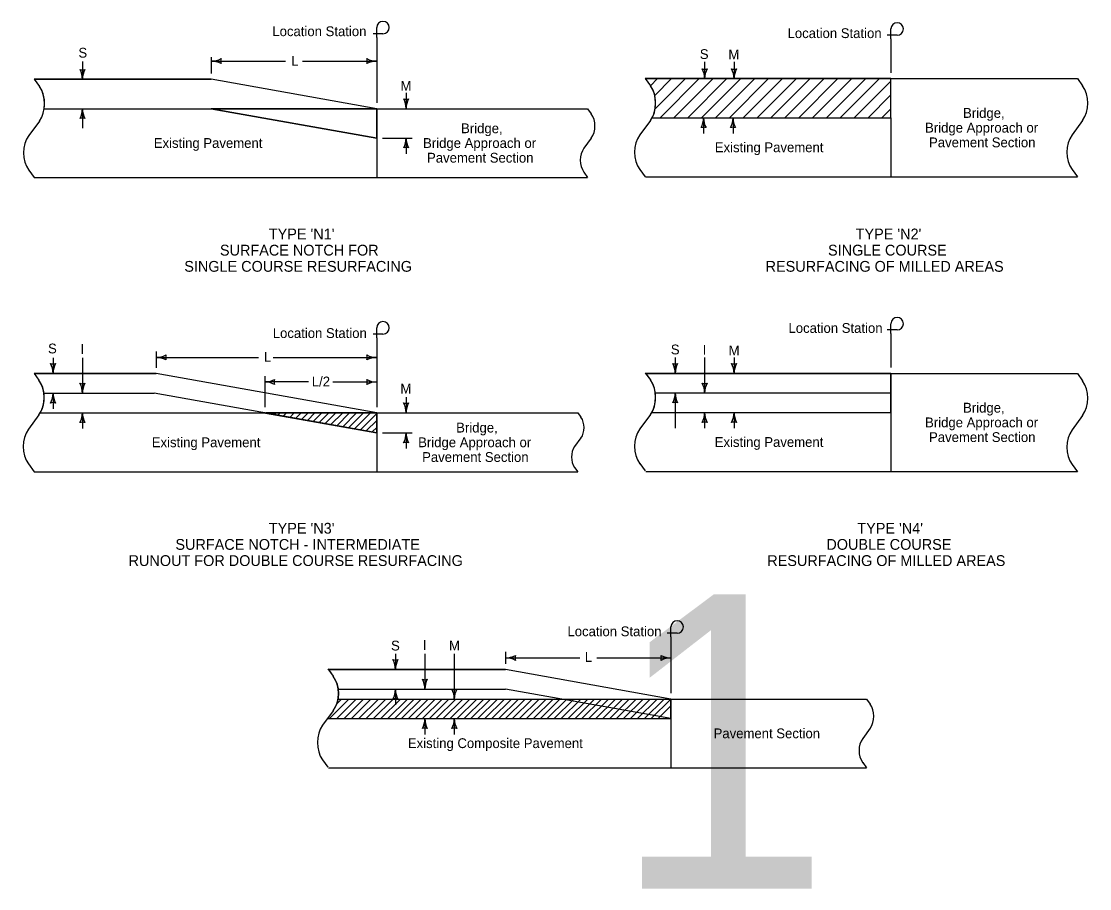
# Model space of a CAD drawing. Extents: x 10133 to 81668, y 7924 to 12178.
# Drawn here: x 10292 to 12471, y 10409 to 12178 of the extents above; entities that cross this region are included whole.
import ezdxf

# ---------------------------------------------------------------- set-up
doc = ezdxf.new("R2010")
doc.units = 0
for name, color, linetype in [('Default', 7, 'Continuous'), ('dsnNonPlotable', 7, 'Continuous'), ('dsnShadingPaved', 7, 'Continuous'), ('dsnShtPlotShapeBatchPrint', 7, 'Continuous'), ('dsnStdBlock', 7, 'Continuous'), ('dsnstdblockInterim', 7, 'Continuous'), ('dsnStdBlockModified', 7, 'Continuous'), ('dsnStdBlockNotModified', 7, 'Continuous'), ('dsnStdBorder', 7, 'Continuous'), ('Level 2', 7, 'Continuous')]:
    doc.layers.add(name, color=color, linetype=linetype)

msp = doc.modelspace()

# ---------------------------------------------------------------- linework, layer by layer
at = {"layer": 'Default'}
for p, q in [((11017.1, 11999.6), (10679.6, 11999.6)), ((10679.6, 11999.6), (11017.1, 11939.6)), ((11017.1, 11939.6), (11017.1, 11999.6))]:
    msp.add_line(p, q, dxfattribs=at)
msp.add_lwpolyline([(10790.5, 11379), (11017.1, 11338.7), (11017.1, 11379.3), (10790.9, 11379.3), (10790.5, 11379)], dxfattribs=at)
at = {"layer": 'dsnNonPlotable'}
for p, q in [((10318.5, 12059.6), (10329.2, 12045)), ((11017.1, 11999.6), (10679.6, 12059.6)), ((12065.7, 12060.9), (11564.4, 12060.9)), ((11564.4, 12060.9), (11575.2, 12046.3)), ((12065.7, 11980.9), (12065.7, 12060.9)), ((10679.6, 11999.6), (11017.1, 11939.6)), ((11017.1, 11939.6), (11017.1, 11999.6)), ((11578.6, 11980.9), (12065.7, 11980.9)), ((10567.1, 11459.3), (10318.5, 11459.3)), ((10318.5, 11459.3), (10328.3, 11446)), ((11017.1, 11379.3), (10567.1, 11459.3)), ((10330.9, 11379.3), (11017.1, 11379.3))]:
    msp.add_line(p, q, dxfattribs=at)
for points in [[(10679.6, 12059.6), (10417.1, 12059.6), (10318.5, 12059.6)], [(10339.2, 11999.6), (10417.1, 11999.6), (10679.6, 11999.6)]]:
    msp.add_lwpolyline(points, dxfattribs=at)
for centre, start_param in [((11549.2, 12010.9), 0.927277), ((10303.3, 12009.6), 1.369431), ((10302.4, 11410.6), 0.895403)]:
    msp.add_ellipse(centre, major_axis=(0, -50), ratio=0.732645, start_param=start_param, end_param=2.356194, dxfattribs=at)
at = {"layer": 'dsnShtPlotShapeBatchPrint'}
for p, q in [((11575.2, 12046.2), (11589.9, 12060.9)), ((11584, 12026.7), (11618.2, 12060.9)), ((11584.9, 11999.3), (11646.5, 12060.9)), ((11594.7, 11980.9), (11674.7, 12060.9)), ((11623, 11980.9), (11703, 12060.9)), ((11651.3, 11980.9), (11731.3, 12060.9)), ((11679.6, 11980.9), (11759.6, 12060.9)), ((11707.9, 11980.9), (11787.9, 12060.9)), ((11736.2, 11980.9), (11816.2, 12060.9)), ((11764.5, 11980.9), (11844.5, 12060.9)), ((11792.7, 11980.9), (11872.7, 12060.9)), ((11821, 11980.9), (11901, 12060.9)), ((11849.3, 11980.9), (11929.3, 12060.9)), ((11877.6, 11980.9), (11957.6, 12060.9)), ((11905.9, 11980.9), (11985.9, 12060.9)), ((11934.2, 11980.9), (12014.2, 12060.9)), ((11962.4, 11980.9), (12042.4, 12060.9)), ((11990.7, 11980.9), (12065.7, 12055.9)), ((12019, 11980.9), (12065.7, 12027.6)), ((12047.3, 11980.9), (12065.7, 11999.3))]:
    msp.add_line(p, q, dxfattribs=at)
at = {"layer": 'dsnStdBlock'}
for p, q in [((11017.1, 12144.6), (11017.1, 12165)), ((12065.7, 12141.9), (12065.7, 12162.2)), ((11029.8, 12152.3), (11009.5, 12152.3)), ((11017.1, 12144.6), (11017.1, 12011.6)), ((12078.4, 12149.5), (12058.1, 12149.5)), ((12065.7, 12141.9), (12065.7, 12072.9)), ((10417.1, 12096), (10417.1, 12059.6)), ((10679.6, 12104.6), (10679.6, 12071.6)), ((10679.6, 12096.6), (10830.9, 12096.6)), ((10865.9, 12096.6), (11017.1, 12096.6)), ((11685.7, 12095.4), (11685.7, 12060.9)), ((11745.7, 12095.4), (11745.7, 12060.9)), ((10318.5, 12059.6), (10679.6, 12059.6)), ((10318.5, 12059.6), (10329.2, 12045)), ((11017.1, 11999.6), (10679.6, 12059.6)), ((11564.4, 12060.9), (12065.7, 12060.9)), ((11564.4, 12060.9), (11575.1, 12046.3)), ((12065.7, 12060.9), (12445.7, 12060.9)), ((12065.7, 11980.9), (12065.7, 12060.9)), ((12445.7, 12060.9), (12456.4, 12046.3)), ((11077.1, 12031.9), (11077.1, 11999.9)), ((10339.2, 11999.6), (10679.6, 11999.6)), ((10417.1, 11999.6), (10417.1, 11960.2)), ((11017.1, 11939.6), (10679.6, 11999.6)), ((10679.6, 11999.6), (11017.1, 11999.6)), ((11017.1, 11999.6), (11446.9, 11999.6)), ((11017.1, 11999.6), (11017.1, 11939.6)), ((11447.1, 11999.4), (11454.6, 11989.1)), ((11578.6, 11980.9), (12065.7, 11980.9)), ((11683.6, 11980.9), (11683.6, 11948.9)), ((11743.6, 11980.9), (11743.6, 11948.9)), ((12065.7, 11980.9), (12065.7, 11860.9)), ((10329.2, 11974.3), (10307.7, 11945)), ((11575.1, 11975.5), (11553.7, 11946.3)), ((12456.4, 11975.5), (12435, 11946.3)), ((11017.1, 11939.6), (11017.1, 11859.6)), ((11029.1, 11939.6), (11089.1, 11939.6)), ((11077.1, 11939.6), (11077.1, 11907.6)), ((11454.6, 11939.7), (11439.6, 11919.3)), ((10307.7, 11874.3), (10318.5, 11859.6)), ((11553.7, 11875.5), (11564.4, 11860.9)), ((12435, 11875.5), (12445.7, 11860.9)), ((10318.5, 11859.6), (11447.1, 11859.6)), ((11439.6, 11869.9), (11447.1, 11859.6)), ((11565.3, 11860.9), (12445.7, 11860.9)), ((11017.1, 11532.3), (11017.1, 11552.7)), ((12078.4, 11548.5), (12058.1, 11548.5)), ((12065.7, 11540.9), (12065.7, 11561.2)), ((11029.8, 11540), (11009.5, 11540)), ((11017.1, 11532.3), (11017.1, 11391.3)), ((12065.7, 11540.9), (12065.7, 11471.9)), ((10567.1, 11504.3), (10567.1, 11471.3)), ((10357.1, 11491.7), (10357.1, 11459.7)), ((10417.1, 11491.7), (10417.1, 11419.3)), ((10567.1, 11492.3), (10776.1, 11492.3)), ((10806.1, 11492.3), (11017.1, 11492.3)), ((11625.7, 11491.9), (11625.7, 11459.9)), ((11685.7, 11491.9), (11685.7, 11419.9)), ((11745.7, 11491.9), (11745.7, 11459.9)), ((10318.5, 11459.3), (10567.1, 11459.3)), ((10318.5, 11459.3), (10328.3, 11446)), ((11017.1, 11379.3), (10567.1, 11459.3)), ((11564.4, 11461.1), (11575.1, 11446.5)), ((11565.7, 11459.9), (12065.7, 11459.9)), ((12065.7, 11459.9), (12065.7, 11379.9)), ((12065.7, 11459.9), (12445.7, 11459.9)), ((12445.7, 11459.9), (12456.4, 11444.7)), ((10788.6, 11454.3), (10788.6, 11391.3)), ((10877.8, 11442.3), (10788.6, 11442.3)), ((10927.8, 11442.3), (11017.1, 11442.3)), ((10338.4, 11419.3), (10563.6, 11419.3)), ((10357.1, 11419.7), (10357.1, 11387.7)), ((11017.1, 11338.7), (10563.6, 11419.3)), ((11585.3, 11419.9), (12065.7, 11419.9)), ((11625.7, 11419.9), (11625.7, 11347.9)), ((11077.1, 11411.3), (11077.1, 11379.3)), ((10328.3, 11375.2), (10306.8, 11346)), ((10330.9, 11379.3), (11017.1, 11379.3)), ((10417.1, 11379.7), (10417.1, 11347.7)), ((10788.6, 11379.3), (10788.6, 11379.3)), ((10789.3, 11379.2), (10789.5, 11379.3)), ((10790.5, 11379), (10790.9, 11379.3)), ((10803.7, 11376.7), (10806.4, 11379.3)), ((10808.5, 11375.8), (10812, 11379.3)), ((10815.7, 11374.5), (10820.5, 11379.3)), ((10826.5, 11372.6), (10833.2, 11379.3)), ((10839.7, 11370.2), (10848.8, 11379.3)), ((10851.7, 11368.1), (10862.9, 11379.3)), ((10863.7, 11366), (10877.1, 11379.3)), ((10875.7, 11363.8), (10891.2, 11379.3)), ((10887.7, 11361.7), (10905.4, 11379.3)), ((10899.7, 11359.6), (10919.5, 11379.3)), ((10911.7, 11357.4), (10933.6, 11379.3)), ((10923.7, 11355.3), (10947.8, 11379.3)), ((10935.8, 11353.2), (10961.9, 11379.3)), ((10947.8, 11351), (10976.1, 11379.3)), ((10959.8, 11348.9), (10990.2, 11379.3)), ((10971.8, 11346.8), (11004.3, 11379.3)), ((10983.8, 11344.6), (11017.1, 11377.9)), ((11017.1, 11379.3), (11427.1, 11379.3)), ((11017.1, 11379.3), (11017.1, 11338.7)), ((11427.1, 11379.3), (11433.5, 11370.5)), ((11575.1, 11375.8), (11553.7, 11346.5)), ((11578.1, 11379.9), (12065.7, 11379.9)), ((11685.7, 11379.9), (11685.7, 11347.9)), ((11745.7, 11379.9), (11745.7, 11347.9)), ((12065.4, 11379.9), (12065.7, 11380.2)), ((12065.7, 11379.9), (12065.7, 11259.9)), ((12456.4, 11374), (12435, 11344.7)), ((10995.8, 11342.5), (11017.1, 11363.8)), ((11007.8, 11340.4), (11017.1, 11349.7)), ((11017.1, 11338.7), (11017.1, 11259.3)), ((11029.1, 11338.7), (11089.1, 11338.7)), ((11077.1, 11338.7), (11077.1, 11306.7)), ((11433.5, 11328.1), (11420.7, 11310.5)), ((10306.8, 11275.2), (10318.8, 11259.3)), ((11420.7, 11268.1), (11427.1, 11259.3)), ((11553.7, 11275.8), (11564.4, 11261.1)), ((12435, 11274), (12445.7, 11259.3)), ((10318.8, 11259.3), (11427.1, 11259.3)), ((11565.7, 11259.9), (12445.7, 11259.9)), ((11617.1, 10922.4), (11617.1, 10942.7)), ((11629.8, 10930), (11609.5, 10930)), ((11617.1, 10922.4), (11617.1, 10807.8)), ((11279.6, 10891.8), (11279.6, 10867.8)), ((11055.3, 10887.8), (11055.3, 10855.8)), ((11115.3, 10887.8), (11115.3, 10815.8)), ((11175.3, 10887.8), (11175.3, 10795.8)), ((11279.6, 10879.8), (11430.9, 10879.8)), ((11465.9, 10879.8), (11617.1, 10879.8)), ((10917.5, 10857.1), (10928.3, 10842.4)), ((10918.5, 10855.8), (11279.6, 10855.8)), ((11617.1, 10795.8), (11279.6, 10855.8)), ((10938.4, 10815.8), (11279.6, 10815.8)), ((11055.3, 10815.8), (11055.3, 10783.8)), ((11175.4, 10814.1), (11177.2, 10815.8)), ((11617.1, 10755.8), (11279.6, 10815.8)), ((10920.5, 10755.8), (10960.4, 10795.8)), ((10935.5, 10755.8), (10975.4, 10795.8)), ((10935.6, 10785.9), (10945.4, 10795.8)), ((10938.1, 10795.8), (11392.1, 10795.8)), ((10950.5, 10755.8), (10990.4, 10795.8)), ((10965.5, 10755.8), (11005.4, 10795.8)), ((10980.5, 10755.8), (11020.4, 10795.8)), ((10995.5, 10755.8), (11035.4, 10795.8)), ((11010.5, 10755.8), (11050.4, 10795.8)), ((11025.5, 10755.8), (11065.4, 10795.8)), ((11039.6, 10755.8), (11079.6, 10795.8)), ((11053.7, 10755.8), (11093.7, 10795.8)), ((11067.9, 10755.8), (11107.9, 10795.8)), ((11082, 10755.8), (11122, 10795.8)), ((11096.2, 10755.8), (11136.2, 10795.8)), ((11110.3, 10755.8), (11150.3, 10795.8)), ((11124.4, 10755.8), (11164.4, 10795.8)), ((11138.6, 10755.8), (11178.6, 10795.8)), ((11152.7, 10755.8), (11192.7, 10795.8)), ((11166.9, 10755.8), (11206.9, 10795.8)), ((11181, 10755.8), (11221, 10795.8)), ((11195.2, 10755.8), (11235.2, 10795.8)), ((11209.3, 10755.8), (11249.3, 10795.8)), ((11223.4, 10755.8), (11263.4, 10795.8)), ((11237.6, 10755.8), (11277.6, 10795.8)), ((11251.7, 10755.8), (11291.7, 10795.8)), ((11265.9, 10755.8), (11305.9, 10795.8)), ((11280, 10755.8), (11320, 10795.8)), ((11294.2, 10755.8), (11334.2, 10795.8)), ((11308.3, 10755.8), (11348.3, 10795.8)), ((11322.4, 10755.8), (11362.4, 10795.8)), ((11336.6, 10755.8), (11376.6, 10795.8)), ((11350.7, 10755.8), (11390.7, 10795.8)), ((11364.9, 10755.8), (11404.9, 10795.8)), ((11379, 10755.8), (11419, 10795.8)), ((11392.1, 10795.8), (11617.1, 10795.8)), ((11393.1, 10755.8), (11433.1, 10795.8)), ((11407.3, 10755.8), (11447.3, 10795.8)), ((11421.4, 10755.8), (11461.4, 10795.8)), ((11435.6, 10755.8), (11475.6, 10795.8)), ((11449.7, 10755.8), (11489.7, 10795.8)), ((11463.9, 10755.8), (11503.9, 10795.8)), ((11478, 10755.8), (11518, 10795.8)), ((11492.1, 10755.8), (11532.1, 10795.8)), ((11506.3, 10755.8), (11546.3, 10795.8)), ((11520.4, 10755.8), (11560.4, 10795.8)), ((11534.6, 10755.8), (11574.6, 10795.8)), ((11548.7, 10755.8), (11588.7, 10795.8)), ((11562.9, 10755.8), (11602.9, 10795.8)), ((11577, 10755.8), (11617, 10795.8)), ((11617.1, 10795.8), (11617.1, 10655.8)), ((11617.1, 10795.8), (12015.6, 10795.8)), ((12015.6, 10795.8), (12023.1, 10785.6)), ((10928.3, 10771.7), (10906.8, 10742.4)), ((11591.1, 10755.8), (11617.1, 10781.8)), ((10916.6, 10755.8), (11617.1, 10755.8)), ((11115.3, 10755.8), (11115.3, 10723.8)), ((11175.3, 10755.8), (11175.3, 10723.8)), ((12023.1, 10736.1), (12008.1, 10715.6)), ((10906.8, 10671.7), (10917.5, 10657.1)), ((10918.5, 10655.8), (12015.6, 10655.8)), ((12008.1, 10666.1), (12015.6, 10655.8))]:
    msp.add_line(p, q, dxfattribs=at)
msp.add_lwpolyline([(10788.6, 11379.3), (11017.1, 11379.3), (11017.1, 11338.7)], close=True, dxfattribs=at)
for centre, radius, start, end in [((11029.8, 12165), 12.7, 270, 180), ((12078.4, 12162.2), 12.7, 270, 180), ((12078.4, 11561.2), 12.7, 270, 180), ((11029.8, 11552.7), 12.7, 270, 180), ((10357.1, 11495.9), 16.7, 252.2666, 287.7333), ((10313.9, 11459.7), 43.2, 360, 28.0725), ((10400.3, 11459.7), 43.2, 151.9275, 180), ((10567.1, 11535.5), 43.2, 270, 298.0725), ((10567.1, 11449.2), 43.2, 61.9275, 90), ((10603.3, 11492.3), 16.7, 162.2666, 197.7334), ((10980.9, 11492.3), 16.7, 342.2666, 17.7333), ((11017.1, 11535.5), 43.2, 241.9275, 270), ((11017.1, 11449.2), 43.2, 90, 118.0725), ((10417.1, 11455.5), 16.7, 252.2666, 287.7333), ((10373.9, 11419.3), 43.2, 360, 28.0725), ((10460.3, 11419.3), 43.2, 151.9275, 180), ((10788.6, 11485.5), 43.2, 270, 298.0725), ((10788.6, 11399.2), 43.2, 61.9275, 90), ((10824.8, 11442.3), 16.7, 162.2666, 197.7334), ((10980.9, 11442.3), 16.7, 342.2666, 17.7333), ((11017.1, 11485.5), 43.2, 241.9275, 270), ((11017.1, 11399.2), 43.2, 90, 118.0725), ((10313.9, 11419.7), 43.2, 331.9275, 360), ((10400.3, 11419.7), 43.2, 180, 208.0725), ((10357.1, 11383.5), 16.7, 72.2666, 107.7334), ((11077.1, 11415.5), 16.7, 252.2666, 287.7333), ((11033.9, 11379.3), 43.2, 360, 28.0725), ((11120.3, 11379.3), 43.2, 151.9275, 180), ((10373.9, 11379.7), 43.2, 331.9275, 360), ((10460.3, 11379.7), 43.2, 180, 208.0725), ((10417.1, 11343.5), 16.7, 72.2666, 107.7334), ((11033.9, 11338.7), 43.2, 331.9275, 360), ((11120.3, 11338.7), 43.2, 180, 208.0725), ((11077.1, 11302.5), 16.7, 72.2666, 107.7334), ((11629.8, 10942.7), 12.7, 270, 180), ((11055.3, 10892), 16.7, 252.2666, 287.7333), ((11012.1, 10855.8), 43.2, 360, 28.0725), ((11098.4, 10855.8), 43.2, 151.9275, 180), ((11279.6, 10923), 43.2, 270, 298.0725), ((11279.6, 10836.6), 43.2, 61.9275, 90), ((11315.8, 10879.8), 16.7, 162.2666, 197.7334), ((11580.9, 10879.8), 16.7, 342.2666, 17.7333), ((11617.1, 10923), 43.2, 241.9275, 270), ((11617.1, 10836.6), 43.2, 90, 118.0725), ((11115.3, 10852), 16.7, 252.2666, 287.7333), ((11072.1, 10815.8), 43.2, 360, 28.0725), ((11158.4, 10815.8), 43.2, 151.9275, 180), ((11012.1, 10815.8), 43.2, 331.9275, 360), ((11098.4, 10815.8), 43.2, 180, 208.0725), ((11175.3, 10832), 16.7, 252.2666, 287.7333), ((11132.1, 10795.8), 43.2, 360, 28.0725), ((11218.4, 10795.8), 43.2, 151.9275, 180), ((11055.3, 10779.6), 16.7, 72.2666, 107.7334), ((11072.1, 10755.8), 43.2, 331.9275, 360), ((11158.4, 10755.8), 43.2, 180, 208.0725), ((11132.1, 10755.8), 43.2, 331.9275, 360), ((11218.4, 10755.8), 43.2, 180, 208.0725), ((11115.3, 10719.6), 16.7, 72.2666, 107.7334), ((11175.3, 10719.6), 16.7, 72.2666, 107.7334)]:
    msp.add_arc(centre, radius, start, end, dxfattribs=at)
for centre, major_axis, ratio in [((11549.2, 12010.9), (0, -50), 0.732645), ((12430.5, 12010.9), (0, -50), 0.732645), ((10303.3, 12009.6), (0, -50), 0.732645), ((11436.5, 11964.4), (0, -34.9), 0.732645), ((10333.6, 11909.6), (0, 50), 0.732645), ((11579.6, 11910.9), (0, 50), 0.732645), ((12460.9, 11910.9), (0, 50), 0.732645), ((11457.7, 11894.6), (0, 34.9), 0.732645), ((10302.4, 11410.6), (0, -50), 0.732645), ((11549.2, 11411.1), (0, -50), 0.732645), ((12430.5, 11409.3), (0, -50), 0.732645), ((11418, 11349.3), (0, -30), 0.732645), ((10332.7, 11310.6), (0, 50), 0.732645), ((11579.6, 11311.1), (0, 50), 0.732645), ((12460.9, 11309.3), (0, 50), 0.732645), ((11436.2, 11289.3), (0, 30), 0.732645), ((10902.4, 10807.1), (0, -50), 0.732645), ((12005, 10760.8), (0, -35), 0.732627), ((10932.7, 10707.1), (0, 50), 0.732645), ((12026.2, 10690.8), (0, 35), 0.732627)]:
    msp.add_ellipse(centre, major_axis=major_axis, ratio=ratio, start_param=0.785398, end_param=2.356194, dxfattribs=at)
at = {"layer": 'dsnStdBlockModified'}
for centre, radius, start, end in [((10679.6, 12139.1), 42.5, 270, 298.0725), ((10679.6, 12054.1), 42.5, 61.9275, 90), ((10715.2, 12096.6), 16.4, 162.2666, 197.7334), ((10981.5, 12096.6), 16.4, 342.2666, 17.7334), ((11017.1, 12139.1), 42.5, 241.9275, 270), ((11017.1, 12054.1), 42.5, 90, 118.0725), ((10417.1, 12095.3), 16.4, 252.2666, 287.7333), ((10374.6, 12059.6), 42.5, 360, 28.0725), ((10459.6, 12059.6), 42.5, 151.9275, 180), ((11685.7, 12096.5), 16.4, 252.2666, 287.7333), ((11643.2, 12060.9), 42.5, 360, 28.0725), ((11728.2, 12060.9), 42.5, 151.9275, 180), ((11745.7, 12096.5), 16.4, 252.2666, 287.7333), ((11703.2, 12060.9), 42.5, 360, 28.0725), ((11788.2, 12060.9), 42.5, 151.9275, 180), ((11077.1, 12035.5), 16.4, 252.2666, 287.7333), ((11034.6, 11999.9), 42.5, 360, 28.0725), ((11119.6, 11999.9), 42.5, 151.9275, 180), ((10374.6, 11999.6), 42.5, 331.9275, 360), ((10417.1, 11964), 16.4, 72.2666, 107.7334), ((10459.6, 11999.6), 42.5, 180, 208.0725), ((11641.1, 11980.9), 42.5, 331.9275, 360), ((11726.1, 11980.9), 42.5, 180, 208.0725), ((11701.1, 11980.9), 42.5, 331.9275, 360), ((11786.1, 11980.9), 42.5, 180, 208.0725), ((11683.6, 11945.3), 16.4, 72.2666, 107.7334), ((11743.6, 11945.3), 16.4, 72.2666, 107.7334), ((11034.6, 11939.6), 42.5, 331.9275, 360), ((11119.6, 11939.6), 42.5, 180, 208.0725), ((11077.1, 11904), 16.4, 72.2666, 107.7334), ((11625.7, 11495.5), 16.4, 252.2666, 287.7333), ((11583.2, 11459.9), 42.5, 360, 28.0725), ((11668.2, 11459.9), 42.5, 151.9275, 180), ((11745.7, 11495.5), 16.4, 252.2666, 287.7333), ((11703.2, 11459.9), 42.5, 360, 28.0725), ((11788.2, 11459.9), 42.5, 151.9275, 180), ((11685.7, 11455.5), 16.4, 252.2666, 287.7333), ((11643.2, 11419.9), 42.5, 360, 28.0725), ((11728.2, 11419.9), 42.5, 151.9275, 180), ((11583.2, 11419.9), 42.5, 331.9275, 360), ((11668.2, 11419.9), 42.5, 180, 208.0725), ((11625.7, 11384.2), 16.4, 72.2666, 107.7334), ((11643.2, 11379.9), 42.5, 331.9275, 360), ((11728.2, 11379.9), 42.5, 180, 208.0725), ((11703.2, 11379.9), 42.5, 331.9275, 360), ((11788.2, 11379.9), 42.5, 180, 208.0725), ((11685.7, 11344.2), 16.4, 72.2666, 107.7334), ((11745.7, 11344.2), 16.4, 72.2666, 107.7334)]:
    msp.add_arc(centre, radius, start, end, dxfattribs=at)
at = {"layer": 'dsnStdBlockNotModified'}
for p, q in [((12065.7, 11459.9), (11565.3, 11459.9)), ((11565.3, 11459.9), (11575.2, 11446.5)), ((12065.7, 11459.9), (11565.3, 11459.9)), ((11565.3, 11459.9), (11575.2, 11446.5)), ((12065.7, 11379.9), (12065.7, 11459.9)), ((12065.7, 11379.9), (12065.7, 11459.9)), ((11577.8, 11379.9), (12065.7, 11379.9)), ((11577.8, 11379.9), (12065.7, 11379.9)), ((11279.6, 10855.8), (10918.5, 10855.8)), ((10918.5, 10855.8), (10928.3, 10842.4)), ((11617.1, 10795.8), (11279.6, 10855.8)), ((11617.1, 10755.8), (11617.1, 10795.8)), ((10928.3, 10771.7), (10916.6, 10755.8)), ((10916.6, 10755.8), (11617.1, 10755.8))]:
    msp.add_line(p, q, dxfattribs=at)
msp.add_arc((10880, 10807.1), 59.8, 323.7718, 36.2282, dxfattribs=at)
msp.add_ellipse((11549.2, 11411.1), major_axis=(0, -50), ratio=0.732645, start_param=0.89539, end_param=2.356194, dxfattribs=at)
msp.add_ellipse((11549.2, 11411.1), major_axis=(0, -50), ratio=0.732645, start_param=0.89539, end_param=2.356194, dxfattribs=at)

# ---------------------------------------------------------------- texts
at = {"layer": 'dsnShadingPaved'}
for s, p in [("TYPE 'N3'", (10797.1, 11133.1)), ('SURFACE NOTCH - INTERMEDIATE', (10606.6, 11100.1)), ('RUNOUT FOR DOUBLE COURSE RESURFACING', (10511.1, 11067.1))]:
    msp.add_text(s, height=22, dxfattribs=at).set_placement(p)
at = {"layer": 'dsnStdBlock'}
for s, p in [('S', (11675.9, 12100.9)), ('M', (11734.2, 12100.1)), ('Bridge,', (12212.7, 11980.9)), ('Bridge,', (11189.1, 11949.6)), ('Bridge Approach or', (12135.2, 11950.9)), ('Existing Pavement', (10562.5, 11919.6)), ('Bridge Approach or', (11111.6, 11919.6)), ('Pavement Section', (12143.3, 11920.9)), ('Existing Pavement', (11706.5, 11910.9)), ('Pavement Section', (11119.7, 11889.6)), ('Bridge,', (12212.7, 11379.9)), ('Bridge Approach or', (12135.2, 11349.9)), ('Bridge,', (11179.1, 11339.3)), ('Existing Pavement', (10558.4, 11309.3)), ('Bridge Approach or', (11101.6, 11309.3)), ('Existing Pavement', (11706.3, 11309.9)), ('Pavement Section', (12143.3, 11319.9)), ('Pavement Section', (11109.7, 11279.3)), ('Pavement Section', (11704, 10715.8)), ('Existing Composite Pavement', (11080.6, 10695.8))]:
    msp.add_text(s, height=20, dxfattribs=at).set_placement(p)
at = {"layer": 'dsnstdblockInterim'}
msp.add_text('1', height=600, dxfattribs=at).set_placement((11496.6, 10409.2))
at = {"layer": 'dsnStdBorder'}
for s, height, p in [('Location Station', 20, (10804.3, 12147.5)), ('Location Station', 20, (11854.8, 12143.6)), ('S', 20, (10408.8, 12103.7)), ('L', 20, (10842.8, 12087.2)), ('M', 20, (11065.6, 12036.1)), ("TYPE 'N1'", 22, (10797.1, 11733.1)), ("TYPE 'N2' ", 22, (11993.7, 11733.1)), ('SURFACE NOTCH FOR', 22, (10697.4, 11700.1)), ('SINGLE COURSE', 22, (11937.3, 11700.1)), ('SINGLE COURSE RESURFACING', 22, (10624.7, 11667.1)), ('RESURFACING OF MILLED AREAS', 22, (11810, 11667.1)), ('Location Station', 20, (10805.1, 11532)), ('Location Station', 20, (11856.7, 11542.4)), ('S', 20, (11616.8, 11498.6)), ('I', 20, (11681.8, 11497.7)), ('M', 20, (11734.7, 11496.5)), ("TYPE 'N4'", 22, (11997.1, 11133.1)), ('DOUBLE COURSE', 22, (11933.9, 11100.1)), ('RESURFACING OF MILLED AREAS', 22, (11813.4, 11067.1)), ('Location Station', 20, (11406, 10923.9)), ('S', 20, (11046.3, 10894.8)), ('I', 20, (11111, 10895.9)), ('M', 20, (11164.5, 10894.9)), ('L', 20, (11441.3, 10871.6))]:
    msp.add_text(s, height=height, dxfattribs=at).set_placement(p)
at = {"layer": 'Level 2'}
for s, p in [('S', (10346.9, 11500.6)), ('I', (10413, 11499.6)), ('L', (10787.1, 11483.6)), ('L/2', (10884.7, 11433.3)), ('M', (11065.4, 11418.7))]:
    msp.add_text(s, height=20, dxfattribs=at).set_placement(p)

doc.saveas('drawing.dxf')
